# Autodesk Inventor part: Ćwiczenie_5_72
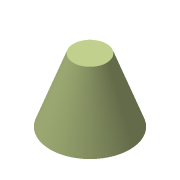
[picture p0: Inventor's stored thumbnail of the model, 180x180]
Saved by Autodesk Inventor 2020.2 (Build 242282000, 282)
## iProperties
Created: 2005-08
Part Number: Ćwiczenie_5_72
Document SubType Name: Modeling
Designer: F.Stasiak
Manufacturer: Standard
Standards Organization: Custom
Density: 1 g/cm^3
Material: Ogólny
Appearance: Chromian cynku 2
Manager: www.cadconsulting.pl
Company: Fabian Stasiak CAD Consulting
Author: F.Stasiak
Subject: Zbiór ćwiczeń. Autodesk Inventor 2020. Kurs podstawowy
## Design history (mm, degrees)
sketch "Szkic1"
  geometry: C1 r 50 at (0, 0); 1 further point
  constraints: 1 centre point, 1 coincident
  dimensions: "d0" = 100 diameter of C1
extrude "Wyciągnięcie proste1" new body sketch "Szkic1" distance "d1" = 80; taper "d2" = -20 deg
node "Bryła1"
node "Korpusy bryłowe"
node "Korpusy powierzchniowe"
